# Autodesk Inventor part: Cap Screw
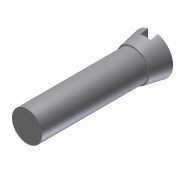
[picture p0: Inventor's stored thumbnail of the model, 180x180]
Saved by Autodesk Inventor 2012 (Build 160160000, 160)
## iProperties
Shininess: 77.0
Length Units: 11269
Angle Units: 11279
Time Units: 11290
Mass Units: 11283
Length Display Precision: 3
Angle Display Precision: 2
Created: 2002-02
Part Number: Cap Screw
Document SubType Name: Modeling
Designer: ***
Density: 1 g/cm^3
Material: Default
Mass: 0.736586 g
Surface Area: 5.87035 cm^2
Volume: 0.736586 cm^3
Density: 0.0
Volumn: 0.0
Area: 0.0
PropertySet Name: Model Information
Control State: 0
Master: False
Checked Out: False
Author: ***
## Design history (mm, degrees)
sketch "Sketch1"
  geometry: L1 (0, 27.83)-(4, 27.83); L2 (4, 27.83)-(3.25, 23.83); L3 (3.25, 23.83)-(0, 23.83); L4 (0, 23.83)-(0, 27.83)
  constraints: 8 end point, 1 horizontal, 1 parallel, 1 perpendicular, 1 point on line
  dimensions: "d2" = 4 distance from line of L1 L2.end; "d5" = 8 diameter of L1.end L4; "d6" = 6.5 diameter of L3.start L4; "d14" = 4 distance of L3.end L1.start
revolve "Revolution1" sketch "Sketch1" stored, may be unused: angle "d7" = 90 deg
sketch "Sketch2"
  geometry: C1 r 3 at (0, 0)
  constraints: 1 centre point
  dimensions: "d8" = 6 diameter of C1
extrude "Extrusion1" join sketch "Sketch2" distance "d9" = 21; taper "d10" = 0 deg
sketch "Sketch3"
  geometry: L1 (-1, 28.967)-(1, 28.967); L2 (1, 28.967)-(1, 26.33); L3 (1, 26.33)-(-1, 26.33); L4 (-1, 26.33)-(-1, 28.967); L5 (-4, 27.83)-(4, 27.83) reference
  constraints: 8 end point, 2 parallel, 1 horizontal, 1 perpendicular
  dimensions: "d11" = 2 distance of L1.start L1.end; "d15" = 1.5 distance between parallel lines of L5 L3
extrude "Extrusion2" cut sketch "Sketch3" stored distance "d12" = 24; taper "d13" = 0 deg
body "Solid1"
